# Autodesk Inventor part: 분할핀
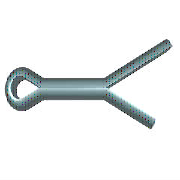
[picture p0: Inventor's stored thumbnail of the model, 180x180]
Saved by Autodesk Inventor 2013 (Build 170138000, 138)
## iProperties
IsCustomPart: 1
Created: 2012-02
Part Number: 분할핀
Material: 강철
Description: 분할 핀
Document SubType Name: Modeling
Standard: ISO 1234
Designer: mdu-01
Standard Revision: Second edition 1997-11-01
Standards Organization: ISO
Language: ko-KR
Size Designation: 2 x 14
Categories: <MemberInstance><Categories><Category DisplayName="조임쇠" InternalName="e4da775c-781d-43d5-af7c-5136215cf5a6" Mnemonic="FSTN"><Category DisplayName="핀" InternalNa
Density: 7.85 g/cm^3
Author: mdu-01
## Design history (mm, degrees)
sketch "스케치1"
  geometry: L1 (0, 0.9)-(8, 0.9); L2 (0, -0.9)-(8, -0.9); L3 (8, 0.9)-(14, 3.199); L4 (14, 3.199)-(14.301, 2.414); L5 (14.301, 2.414)-(8, 0); L6 (8, 0)-(16.801, -3.372); L7 (16.801, -3.372)-(16.5, -4.157); L8 (16.5, -4.157)-(8, -0.9); L9 (0, 0)-(-1.832, -0.821); L10 (0, 0)-(-1.832, 0.821); L11 (0, 0.9)-(0, -0.9); L12 (0, 0.9)-(-1.384, 1.604); L13 (0, -0.9)-(-1.384, -1.604); L14 (-4, 0)-(8, 0); L15 (8, 0.9)-(8, -0.9); A1 r 1.8 centre (-2.2, 0) between (-1.384, 1.604) and (-1.384, -1.604); A2 r 0.9 centre (-2.2, 0) between (-1.832, 0.821) and (-1.832, -0.821); 1 further point
  constraints: 30 end point, 5 point on circle, 4 parallel, 4 perpendicular, 4 point on line, 4 tangent, 2 centre point, 2 midpoint, 1 coincident, 1 horizontal
  dimensions: "d0" = 8 distance of L1.start L1.end (= MSIAB); "d1" = 14 horizontal distance of L1.start L3.end (= SNLG); "d2" = 159.037 deg angle of L1 L3; "d3" = 159.037 deg angle of L2 L8; "d4" = 2.5 horizontal distance of L3.end L7.end (= LGDIF); "d5" = 0.9 radius of A2 (= -0.5 x SNND1 + 0.5 x KBR); "d6" = 1.8 radius of A1 (= 0.5 x KBR); "d7" = 0.9 distance from line of L1 L9.start (= 0.5 x SNND1); "d8" = 0.9 distance between parallel lines of L2 L14 (= 0.5 x SNND1); "d9" = 2.2 distance from line of L11 A1.centre (= KOL - 0.5 x KBR)
extrude "본체" new body sketch "스케치1" stored distance "d10" = 1.8 (= SNND1); taper "d11" = 0 deg
workaxis "Work Axis1"
workplane "Work Plane1"
body "Solid1"
fillet "모깎기" dims "d12" = 0.72 (= 0.4 x SNND1)
node "작업 평면2"
other parameters: "SNND" = 2 [user parameter], "SNLG" = 14 [user parameter; used in 1 equation term], "SNND1" = 1.8 [user parameter; used in 5 equation terms], "KBR" = 3.6 [user parameter; used in 3 equation terms], "KOL" = 4 [user parameter; used in 1 equation term], "LGDIF" = 2.5 [user parameter; used in 1 equation term], "MSIAB" = 8 [user parameter; used in 1 equation term], "d15" = 0, "d16" = 0, "d17" = 0, "NNDMAX" = 9 [user parameter], "DSH" = 4 [user parameter], "NNDMIN" = 7 [user parameter]
